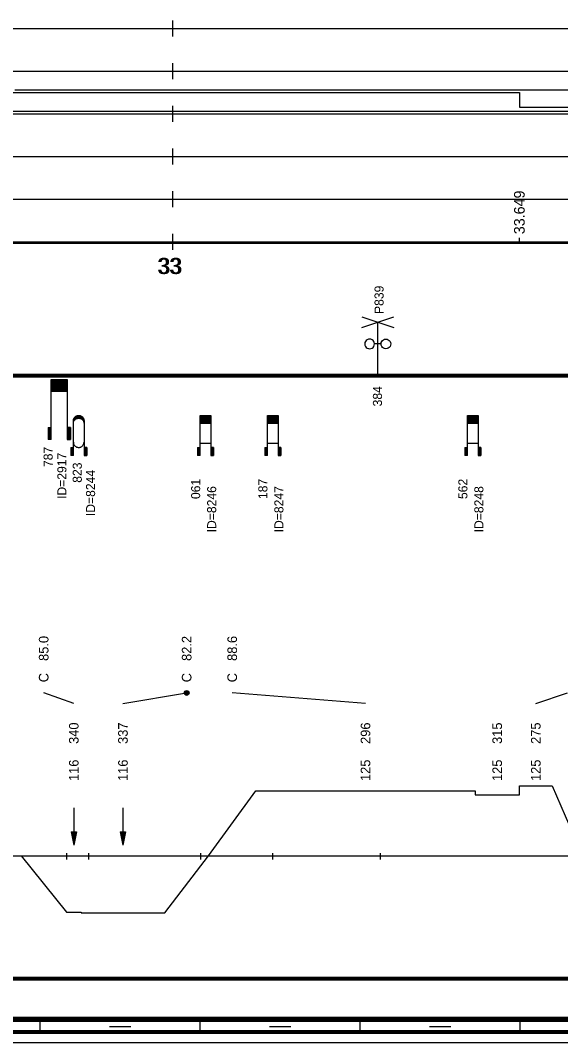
# Model space of a CAD drawing. Extents: x 2 to 10148, y 0 to 380.
# Drawn here: x 3571.3 to 3672.6, y 0 to 191.5 of the extents above; entities that cross this region are included whole.
import ezdxf

# ---------------------------------------------------------------- set-up
doc = ezdxf.new("R2010")
doc.units = 0
for name, color, linetype in [('CARA_S_OBJEKTY', 7, 'Continuous'), ('KRIV1_CARA', 7, 'Continuous'), ('KRIV1_TEXT', 7, 'Continuous'), ('OBJEKTY_TEXT', 7, 'Continuous'), ('OBJEKTY_TVAR', 7, 'Continuous'), ('RAM', 7, 'Continuous'), ('RYCHL_A', 7, 'Continuous'), ('RYCHL_B', 7, 'Continuous'), ('RYCHL_C', 7, 'Continuous'), ('RYCHL_RASTR', 7, 'Continuous'), ('RYCHL_STAN', 7, 'Continuous'), ('STAN_CARA', 7, 'Continuous'), ('STANIC_ZMEN_V', 7, 'Continuous')]:
    doc.layers.add(name, color=color, linetype=linetype)

msp = doc.modelspace()

# ---------------------------------------------------------------- linework, layer by layer
for p, q in [((3579.94, 35.51), (3579.94, 34.32)), ((3584.11, 35.51), (3584.11, 34.32)), ((3605.1, 35.51), (3605.1, 34.32)), ((3618.6, 35.51), (3618.6, 34.32)), ((3638.77, 35.51), (3638.77, 34.32))]:
    msp.add_line(p, q)
at = {"layer": 'CARA_S_OBJEKTY'}
for p, q in [((3155.54, 125.25), (4045.76, 125.25)), ((3155.54, 125), (4045.76, 125)), ((3155.54, 124.75), (4045.76, 124.75))]:
    msp.add_line(p, q, dxfattribs=at)
at = {"layer": 'KRIV1_CARA'}
for p, q in [((3664.85, 46.43), (3664.85, 48.09)), ((3664.85, 48.09), (3671, 48.09)), ((3671, 48.09), (3676.7, 35)), ((3606.59, 35), (3615.45, 47.16)), ((3615.45, 47.16), (3656.54, 47.16)), ((3656.54, 47.16), (3656.54, 46.43)), ((3656.54, 46.43), (3664.85, 46.43)), ((3155.54, 35), (4045.76, 35)), ((3571.43, 35), (3579.93, 24.41)), ((3598.37, 24.32), (3606.59, 35)), ((3579.93, 24.41), (3582.72, 24.41)), ((3582.72, 24.41), (3582.72, 24.32)), ((3582.72, 24.32), (3598.37, 24.32))]:
    msp.add_line(p, q, dxfattribs=at)
at = {"layer": 'KRIV1_TEXT'}
for p, q in [((3581.32, 63.5), (3575.68, 65.5)), ((3590.54, 63.5), (3602.48, 65.5)), ((3636, 63.5), (3611.02, 65.5)), ((3667.93, 63.5), (3673.85, 65.5)), ((3581.32, 44), (3581.32, 42.2)), ((3581.32, 42.2), (3581.32, 40)), ((3590.54, 44), (3590.54, 42.2)), ((3590.54, 42.2), (3590.54, 40)), ((3580.82, 39.5), (3581.32, 37)), ((3580.82, 39.5), (3581.82, 39.5)), ((3580.92, 39.5), (3581.32, 37.5)), ((3581.02, 39.5), (3581.32, 38)), ((3581.12, 39.5), (3581.32, 38.5)), ((3581.22, 39.5), (3581.32, 39)), ((3581.32, 40), (3581.32, 37)), ((3581.82, 39.5), (3581.32, 37)), ((3581.72, 39.5), (3581.32, 37.5)), ((3581.62, 39.5), (3581.32, 38)), ((3581.52, 39.5), (3581.32, 38.5)), ((3581.42, 39.5), (3581.32, 39)), ((3581.32, 39.5), (3581.32, 39.5)), ((3581.32, 39.5), (3581.32, 39.5)), ((3590.04, 39.5), (3590.54, 37)), ((3590.04, 39.5), (3591.04, 39.5)), ((3590.14, 39.5), (3590.54, 37.5)), ((3590.24, 39.5), (3590.54, 38)), ((3590.34, 39.5), (3590.54, 38.5)), ((3590.44, 39.5), (3590.54, 39)), ((3590.54, 40), (3590.54, 37)), ((3591.04, 39.5), (3590.54, 37)), ((3590.94, 39.5), (3590.54, 37.5)), ((3590.84, 39.5), (3590.54, 38)), ((3590.74, 39.5), (3590.54, 38.5)), ((3590.64, 39.5), (3590.54, 39)), ((3590.54, 39.5), (3590.54, 39.5)), ((3590.54, 39.5), (3590.54, 39.5))]:
    msp.add_line(p, q, dxfattribs=at)
for radius in [0.45, 0.3, 0.15]:
    msp.add_circle((3602.48, 65.5), radius, dxfattribs=at)
at = {"layer": 'OBJEKTY_TVAR'}
for p, q in [((3635.29, 134), (3641.29, 136)), ((3635.29, 136), (3641.29, 134)), ((3638.29, 125), (3638.29, 135)), ((3635.89, 131.13), (3635.86, 130.89)), ((3635.86, 130.89), (3635.89, 130.66)), ((3635.98, 131.35), (3635.89, 131.13)), ((3635.89, 130.66), (3635.98, 130.44)), ((3636.13, 131.54), (3635.98, 131.35)), ((3635.98, 130.44), (3636.13, 130.25)), ((3636.32, 131.68), (3636.13, 131.54)), ((3636.13, 130.25), (3636.32, 130.1)), ((3636.54, 131.77), (3636.32, 131.68)), ((3636.77, 131.81), (3636.54, 131.77)), ((3637.01, 131.77), (3636.77, 131.81)), ((3637.23, 131.68), (3637.01, 131.77)), ((3637.42, 131.54), (3637.23, 131.68)), ((3637.23, 130.1), (3637.42, 130.25)), ((3637.56, 131.35), (3637.42, 131.54)), ((3637.42, 130.25), (3637.56, 130.44)), ((3637.65, 131.13), (3637.56, 131.35)), ((3637.56, 130.44), (3637.65, 130.66)), ((3637.68, 130.89), (3637.65, 131.13)), ((3637.65, 130.66), (3637.68, 130.89)), ((3638.92, 130.89), (3637.68, 130.89)), ((3638.92, 130.89), (3638.95, 131.13)), ((3638.95, 130.66), (3638.92, 130.89)), ((3638.95, 131.13), (3639.04, 131.35)), ((3639.04, 130.44), (3638.95, 130.66)), ((3639.04, 131.35), (3639.18, 131.54)), ((3639.18, 130.25), (3639.04, 130.44)), ((3639.18, 131.54), (3639.37, 131.68)), ((3639.37, 130.1), (3639.18, 130.25)), ((3639.37, 131.68), (3639.59, 131.77)), ((3639.59, 131.77), (3639.83, 131.81)), ((3639.83, 131.81), (3640.06, 131.77)), ((3640.06, 131.77), (3640.28, 131.68)), ((3640.28, 131.68), (3640.47, 131.54)), ((3640.47, 130.25), (3640.28, 130.1)), ((3640.47, 131.54), (3640.62, 131.35)), ((3640.62, 130.44), (3640.47, 130.25)), ((3640.62, 131.35), (3640.71, 131.13)), ((3640.71, 130.66), (3640.62, 130.44)), ((3640.71, 131.13), (3640.74, 130.89)), ((3640.74, 130.89), (3640.71, 130.66)), ((3636.32, 130.1), (3636.54, 130.01)), ((3636.54, 130.01), (3636.77, 129.98)), ((3636.77, 129.98), (3637.01, 130.01)), ((3637.01, 130.01), (3637.23, 130.1)), ((3639.59, 130.01), (3639.37, 130.1)), ((3639.83, 129.98), (3639.59, 130.01)), ((3640.06, 130.01), (3639.83, 129.98)), ((3640.28, 130.1), (3640.06, 130.01)), ((3577.09, 124.25), (3580.09, 124.25)), ((3577.09, 113), (3577.09, 124.25)), ((3577.09, 124.17), (3580.09, 124.17)), ((3577.09, 124.1), (3580.09, 124.1)), ((3577.09, 124.02), (3580.09, 124.02)), ((3577.09, 123.95), (3580.09, 123.95)), ((3577.09, 123.87), (3580.09, 123.87)), ((3577.09, 123.8), (3580.09, 123.8)), ((3577.09, 123.72), (3580.09, 123.72)), ((3577.09, 123.65), (3580.09, 123.65)), ((3577.09, 123.57), (3580.09, 123.57)), ((3577.09, 123.5), (3580.09, 123.5)), ((3577.09, 123.42), (3580.09, 123.42)), ((3577.09, 123.35), (3580.09, 123.35)), ((3577.09, 123.27), (3580.09, 123.27)), ((3577.09, 123.2), (3580.09, 123.2)), ((3577.09, 123.12), (3580.09, 123.12)), ((3577.09, 123.05), (3580.09, 123.05)), ((3577.09, 122.97), (3580.09, 122.97)), ((3577.09, 122.9), (3580.09, 122.9)), ((3577.09, 122.82), (3580.09, 122.82)), ((3577.09, 122.75), (3580.09, 122.75)), ((3577.09, 122.67), (3580.09, 122.67)), ((3577.09, 122.6), (3580.09, 122.6)), ((3580.09, 124.25), (3580.09, 113)), ((3577.09, 122.52), (3580.09, 122.52)), ((3577.09, 122.45), (3580.09, 122.45)), ((3577.09, 122.37), (3580.09, 122.37)), ((3577.09, 122.3), (3580.09, 122.3)), ((3577.09, 122.22), (3580.09, 122.22)), ((3577.09, 122.15), (3580.09, 122.15)), ((3577.09, 122.07), (3580.09, 122.07)), ((3581.29, 116.81), (3581.35, 116.95)), ((3581.3, 116.85), (3581.75, 116.85)), ((3581.32, 116.9), (3581.86, 116.9)), ((3581.35, 116.95), (3581.41, 117.06)), ((3581.35, 116.95), (3582.01, 116.95)), ((3581.37, 117), (3583.11, 117)), ((3581.4, 117.05), (3583.08, 117.05)), ((3581.41, 117.06), (3581.5, 117.18)), ((3581.44, 117.1), (3583.04, 117.1)), ((3581.48, 117.15), (3583, 117.15)), ((3581.5, 117.18), (3581.59, 117.26)), ((3581.53, 117.2), (3582.95, 117.2)), ((3581.58, 117.25), (3582.9, 117.25)), ((3581.59, 117.26), (3581.72, 117.35)), ((3581.59, 116.74), (3581.72, 116.83)), ((3581.64, 117.3), (3582.84, 117.3)), ((3581.71, 117.35), (3582.77, 117.35)), ((3581.72, 117.35), (3581.85, 117.42)), ((3581.72, 116.83), (3581.85, 116.9)), ((3581.8, 117.4), (3582.68, 117.4)), ((3581.85, 117.42), (3581.88, 117.43)), ((3581.85, 116.9), (3581.88, 116.91)), ((3581.88, 117.43), (3582, 117.47)), ((3581.88, 116.91), (3582, 116.95)), ((3581.93, 117.45), (3582.55, 117.45)), ((3582, 117.47), (3582.14, 117.49)), ((3582, 116.95), (3582.14, 116.97)), ((3582.14, 117.49), (3582.25, 117.5)), ((3582.14, 116.97), (3582.25, 116.98)), ((3582.25, 117.5), (3582.38, 117.49)), ((3582.25, 116.98), (3582.38, 116.97)), ((3582.38, 117.49), (3582.51, 117.46)), ((3582.38, 116.97), (3582.51, 116.94)), ((3582.47, 116.95), (3583.13, 116.95)), ((3582.51, 117.46), (3582.62, 117.43)), ((3582.51, 116.94), (3582.62, 116.9)), ((3582.62, 117.43), (3582.73, 117.37)), ((3582.62, 116.9), (3582.73, 116.85)), ((3582.62, 116.9), (3583.16, 116.9)), ((3582.73, 117.37), (3582.8, 117.32)), ((3582.73, 116.85), (3583.18, 116.85)), ((3582.73, 116.85), (3582.8, 116.8)), ((3582.8, 117.32), (3582.95, 117.21)), ((3582.95, 117.21), (3583.03, 117.11)), ((3583.03, 117.11), (3583.12, 116.98)), ((3583.12, 116.98), (3583.16, 116.89)), ((3583.16, 116.89), (3583.2, 116.77)), ((3605.02, 110), (3605.02, 117.5)), ((3605.02, 117.5), (3607.02, 117.5)), ((3605.02, 117.45), (3607.02, 117.45)), ((3605.02, 117.4), (3607.02, 117.4)), ((3605.02, 117.35), (3607.02, 117.35)), ((3605.02, 117.3), (3607.02, 117.3)), ((3605.02, 117.25), (3607.02, 117.25)), ((3605.02, 117.2), (3607.02, 117.2)), ((3605.02, 117.15), (3607.02, 117.15)), ((3605.02, 117.1), (3607.02, 117.1)), ((3605.02, 117.05), (3607.02, 117.05)), ((3605.02, 117), (3607.02, 117)), ((3605.02, 116.95), (3607.02, 116.95)), ((3605.02, 116.9), (3607.02, 116.9)), ((3605.02, 116.85), (3607.02, 116.85)), ((3607.02, 117.5), (3607.02, 110)), ((3617.62, 110), (3617.62, 117.5)), ((3617.62, 117.5), (3619.62, 117.5)), ((3617.62, 117.45), (3619.62, 117.45)), ((3617.62, 117.4), (3619.62, 117.4)), ((3617.62, 117.35), (3619.62, 117.35)), ((3617.62, 117.3), (3619.62, 117.3)), ((3617.62, 117.25), (3619.62, 117.25)), ((3617.62, 117.2), (3619.62, 117.2)), ((3617.62, 117.15), (3619.62, 117.15)), ((3617.62, 117.1), (3619.62, 117.1)), ((3617.62, 117.05), (3619.62, 117.05)), ((3617.62, 117), (3619.62, 117)), ((3617.62, 116.95), (3619.62, 116.95)), ((3617.62, 116.9), (3619.62, 116.9)), ((3617.62, 116.85), (3619.62, 116.85)), ((3619.62, 117.5), (3619.62, 110)), ((3655.11, 110), (3655.11, 117.5)), ((3655.11, 117.5), (3657.11, 117.5)), ((3655.11, 117.45), (3657.11, 117.45)), ((3655.11, 117.4), (3657.11, 117.4)), ((3655.11, 117.35), (3657.11, 117.35)), ((3655.11, 117.3), (3657.11, 117.3)), ((3655.11, 117.25), (3657.11, 117.25)), ((3655.11, 117.2), (3657.11, 117.2)), ((3655.11, 117.15), (3657.11, 117.15)), ((3655.11, 117.1), (3657.11, 117.1)), ((3655.11, 117.05), (3657.11, 117.05)), ((3655.11, 117), (3657.11, 117)), ((3655.11, 116.95), (3657.11, 116.95)), ((3655.11, 116.9), (3657.11, 116.9)), ((3655.11, 116.85), (3657.11, 116.85)), ((3657.11, 117.5), (3657.11, 110)), ((3576.49, 115.25), (3576.49, 113)), ((3576.49, 115.25), (3577.09, 115.25)), ((3576.56, 115.25), (3576.56, 113)), ((3576.64, 115.25), (3576.64, 113)), ((3576.71, 115.25), (3576.71, 113)), ((3576.79, 115.25), (3576.79, 113)), ((3576.86, 115.25), (3576.86, 113)), ((3576.94, 115.25), (3576.94, 113)), ((3577.01, 115.25), (3577.01, 113)), ((3580.69, 115.25), (3580.09, 115.25)), ((3580.17, 115.25), (3580.17, 113)), ((3580.24, 115.25), (3580.24, 113)), ((3580.32, 115.25), (3580.32, 113)), ((3580.39, 115.25), (3580.39, 113)), ((3580.47, 115.25), (3580.47, 113)), ((3580.54, 115.25), (3580.54, 113)), ((3580.62, 115.25), (3580.62, 113)), ((3580.69, 115.25), (3580.69, 113)), ((3581.24, 116.5), (3581.25, 116.65)), ((3581.24, 116.55), (3581.42, 116.55)), ((3581.24, 110), (3581.24, 116.5)), ((3581.24, 116.5), (3581.39, 116.5)), ((3581.24, 116.45), (3581.36, 116.45)), ((3581.24, 116.4), (3581.33, 116.4)), ((3581.24, 116.35), (3581.31, 116.35)), ((3581.24, 116.3), (3581.29, 116.3)), ((3581.24, 116.25), (3581.28, 116.25)), ((3581.24, 116.2), (3581.27, 116.2)), ((3581.24, 116.15), (3581.26, 116.15)), ((3581.24, 115.98), (3581.25, 116.13)), ((3581.24, 116.1), (3581.25, 116.1)), ((3581.25, 116.65), (3581.29, 116.81)), ((3581.25, 116.65), (3581.5, 116.65)), ((3581.25, 116.6), (3581.46, 116.6)), ((3581.25, 116.13), (3581.29, 116.28)), ((3581.26, 116.7), (3581.55, 116.7)), ((3581.27, 116.75), (3581.61, 116.75)), ((3581.29, 116.8), (3581.67, 116.8)), ((3581.29, 116.28), (3581.35, 116.43)), ((3581.35, 116.43), (3581.41, 116.53)), ((3581.41, 116.53), (3581.5, 116.65)), ((3581.5, 116.65), (3581.59, 116.74)), ((3582.8, 116.8), (3582.95, 116.68)), ((3582.81, 116.8), (3583.19, 116.8)), ((3582.87, 116.75), (3583.21, 116.75)), ((3582.93, 116.7), (3583.22, 116.7)), ((3582.95, 116.68), (3583.03, 116.59)), ((3582.98, 116.65), (3583.23, 116.65)), ((3583.02, 116.6), (3583.23, 116.6)), ((3583.03, 116.59), (3583.12, 116.46)), ((3583.06, 116.55), (3583.24, 116.55)), ((3583.09, 116.5), (3583.24, 116.5)), ((3583.12, 116.46), (3583.16, 116.37)), ((3583.12, 116.45), (3583.24, 116.45)), ((3583.15, 116.4), (3583.24, 116.4)), ((3583.16, 116.37), (3583.2, 116.24)), ((3583.17, 116.35), (3583.24, 116.35)), ((3583.19, 116.3), (3583.24, 116.3)), ((3583.2, 116.77), (3583.23, 116.65)), ((3583.2, 116.25), (3583.24, 116.25)), ((3583.2, 116.24), (3583.23, 116.13)), ((3583.21, 116.2), (3583.24, 116.2)), ((3583.22, 116.15), (3583.24, 116.15)), ((3583.23, 116.65), (3583.24, 116.56)), ((3583.23, 116.13), (3583.24, 116.03)), ((3583.23, 116.1), (3583.24, 116.1)), ((3583.24, 116.56), (3583.24, 116.5)), ((3583.24, 116.5), (3583.24, 110)), ((3583.24, 116.03), (3583.24, 115.98)), ((3605.02, 116.8), (3607.02, 116.8)), ((3605.02, 116.75), (3607.02, 116.75)), ((3605.02, 116.7), (3607.02, 116.7)), ((3605.02, 116.65), (3607.02, 116.65)), ((3605.02, 116.6), (3607.02, 116.6)), ((3605.02, 116.55), (3607.02, 116.55)), ((3605.02, 116.5), (3607.02, 116.5)), ((3605.02, 116.45), (3607.02, 116.45)), ((3605.02, 116.4), (3607.02, 116.4)), ((3605.02, 116.35), (3607.02, 116.35)), ((3605.02, 116.3), (3607.02, 116.3)), ((3605.02, 116.25), (3607.02, 116.25)), ((3605.02, 116.2), (3607.02, 116.2)), ((3605.02, 116.15), (3607.02, 116.15)), ((3605.02, 116.1), (3607.02, 116.1)), ((3605.02, 116.05), (3607.02, 116.05)), ((3617.62, 116.8), (3619.62, 116.8)), ((3617.62, 116.75), (3619.62, 116.75)), ((3617.62, 116.7), (3619.62, 116.7)), ((3617.62, 116.65), (3619.62, 116.65)), ((3617.62, 116.6), (3619.62, 116.6)), ((3617.62, 116.55), (3619.62, 116.55)), ((3617.62, 116.5), (3619.62, 116.5)), ((3617.62, 116.45), (3619.62, 116.45)), ((3617.62, 116.4), (3619.62, 116.4)), ((3617.62, 116.35), (3619.62, 116.35)), ((3617.62, 116.3), (3619.62, 116.3)), ((3617.62, 116.25), (3619.62, 116.25)), ((3617.62, 116.2), (3619.62, 116.2)), ((3617.62, 116.15), (3619.62, 116.15)), ((3617.62, 116.1), (3619.62, 116.1)), ((3617.62, 116.05), (3619.62, 116.05)), ((3655.11, 116.8), (3657.11, 116.8)), ((3655.11, 116.75), (3657.11, 116.75)), ((3655.11, 116.7), (3657.11, 116.7)), ((3655.11, 116.65), (3657.11, 116.65)), ((3655.11, 116.6), (3657.11, 116.6)), ((3655.11, 116.55), (3657.11, 116.55)), ((3655.11, 116.5), (3657.11, 116.5)), ((3655.11, 116.45), (3657.11, 116.45)), ((3655.11, 116.4), (3657.11, 116.4)), ((3655.11, 116.35), (3657.11, 116.35)), ((3655.11, 116.3), (3657.11, 116.3)), ((3655.11, 116.25), (3657.11, 116.25)), ((3655.11, 116.2), (3657.11, 116.2)), ((3655.11, 116.15), (3657.11, 116.15)), ((3655.11, 116.1), (3657.11, 116.1)), ((3655.11, 116.05), (3657.11, 116.05)), ((3577.09, 113), (3576.49, 113)), ((3580.09, 113), (3580.69, 113)), ((3580.74, 111.5), (3581.24, 111.5)), ((3580.74, 111.5), (3580.74, 110)), ((3580.79, 111.5), (3580.79, 110)), ((3580.84, 111.5), (3580.84, 110)), ((3580.89, 111.5), (3580.89, 110)), ((3580.94, 111.5), (3580.94, 110)), ((3580.99, 111.5), (3580.99, 110)), ((3581.04, 111.5), (3581.04, 110)), ((3581.09, 111.5), (3581.09, 110)), ((3581.14, 111.5), (3581.14, 110)), ((3581.19, 111.5), (3581.19, 110)), ((3581.24, 112.5), (3581.25, 112.35)), ((3581.25, 112.35), (3581.29, 112.2)), ((3581.29, 112.2), (3581.35, 112.05)), ((3581.35, 112.05), (3581.41, 111.95)), ((3581.41, 111.95), (3581.5, 111.83)), ((3581.5, 111.83), (3581.59, 111.74)), ((3581.59, 111.74), (3581.72, 111.65)), ((3581.72, 111.65), (3581.85, 111.58)), ((3581.85, 111.58), (3581.88, 111.57)), ((3581.88, 111.57), (3582, 111.53)), ((3582, 111.53), (3582.14, 111.51)), ((3582.14, 111.51), (3582.25, 111.5)), ((3582.25, 111.5), (3582.38, 111.51)), ((3582.38, 111.51), (3582.51, 111.54)), ((3582.51, 111.54), (3582.62, 111.58)), ((3582.62, 111.58), (3582.73, 111.63)), ((3582.73, 111.63), (3582.8, 111.68)), ((3582.8, 111.68), (3582.95, 111.8)), ((3582.95, 111.8), (3583.03, 111.9)), ((3583.03, 111.9), (3583.12, 112.02)), ((3583.12, 112.02), (3583.16, 112.11)), ((3583.16, 112.11), (3583.2, 112.24)), ((3583.2, 112.24), (3583.23, 112.35)), ((3583.23, 112.35), (3583.24, 112.45)), ((3583.24, 112.45), (3583.24, 112.5)), ((3583.74, 111.5), (3583.24, 111.5)), ((3583.29, 111.5), (3583.29, 110)), ((3583.34, 111.5), (3583.34, 110)), ((3583.39, 111.5), (3583.39, 110)), ((3583.44, 111.5), (3583.44, 110)), ((3583.49, 111.5), (3583.49, 110)), ((3583.54, 111.5), (3583.54, 110)), ((3583.59, 111.5), (3583.59, 110)), ((3583.64, 111.5), (3583.64, 110)), ((3583.69, 111.5), (3583.69, 110)), ((3583.74, 111.5), (3583.74, 110)), ((3604.52, 111.5), (3605.02, 111.5)), ((3604.52, 111.5), (3604.52, 110)), ((3604.57, 111.5), (3604.57, 110)), ((3604.62, 111.5), (3604.62, 110)), ((3604.67, 111.5), (3604.67, 110)), ((3604.72, 111.5), (3604.72, 110)), ((3604.77, 111.5), (3604.77, 110)), ((3604.82, 111.5), (3604.82, 110)), ((3604.87, 111.5), (3604.87, 110)), ((3604.92, 111.5), (3604.92, 110)), ((3604.97, 111.5), (3604.97, 110)), ((3605.02, 112.31), (3607.02, 112.31)), ((3607.52, 111.5), (3607.02, 111.5)), ((3607.07, 111.5), (3607.07, 110)), ((3607.12, 111.5), (3607.12, 110)), ((3607.17, 111.5), (3607.17, 110)), ((3607.22, 111.5), (3607.22, 110)), ((3607.27, 111.5), (3607.27, 110)), ((3607.32, 111.5), (3607.32, 110)), ((3607.37, 111.5), (3607.37, 110)), ((3607.42, 111.5), (3607.42, 110)), ((3607.47, 111.5), (3607.47, 110)), ((3607.52, 111.5), (3607.52, 110)), ((3617.12, 111.5), (3617.62, 111.5)), ((3617.12, 111.5), (3617.12, 110)), ((3617.17, 111.5), (3617.17, 110)), ((3617.22, 111.5), (3617.22, 110)), ((3617.27, 111.5), (3617.27, 110)), ((3617.32, 111.5), (3617.32, 110)), ((3617.37, 111.5), (3617.37, 110)), ((3617.42, 111.5), (3617.42, 110)), ((3617.47, 111.5), (3617.47, 110)), ((3617.52, 111.5), (3617.52, 110)), ((3617.57, 111.5), (3617.57, 110)), ((3617.62, 112.31), (3619.62, 112.31)), ((3620.12, 111.5), (3619.62, 111.5)), ((3619.67, 111.5), (3619.67, 110)), ((3619.72, 111.5), (3619.72, 110)), ((3619.77, 111.5), (3619.77, 110)), ((3619.82, 111.5), (3619.82, 110)), ((3619.87, 111.5), (3619.87, 110)), ((3619.92, 111.5), (3619.92, 110)), ((3619.97, 111.5), (3619.97, 110)), ((3620.02, 111.5), (3620.02, 110)), ((3620.07, 111.5), (3620.07, 110)), ((3620.12, 111.5), (3620.12, 110)), ((3654.61, 111.5), (3655.11, 111.5)), ((3654.61, 111.5), (3654.61, 110)), ((3654.66, 111.5), (3654.66, 110)), ((3654.71, 111.5), (3654.71, 110)), ((3654.76, 111.5), (3654.76, 110)), ((3654.81, 111.5), (3654.81, 110)), ((3654.86, 111.5), (3654.86, 110)), ((3654.91, 111.5), (3654.91, 110)), ((3654.96, 111.5), (3654.96, 110)), ((3655.01, 111.5), (3655.01, 110)), ((3655.06, 111.5), (3655.06, 110)), ((3655.11, 112.31), (3657.11, 112.31)), ((3657.61, 111.5), (3657.11, 111.5)), ((3657.16, 111.5), (3657.16, 110)), ((3657.21, 111.5), (3657.21, 110)), ((3657.26, 111.5), (3657.26, 110)), ((3657.31, 111.5), (3657.31, 110)), ((3657.36, 111.5), (3657.36, 110)), ((3657.41, 111.5), (3657.41, 110)), ((3657.46, 111.5), (3657.46, 110)), ((3657.51, 111.5), (3657.51, 110)), ((3657.56, 111.5), (3657.56, 110)), ((3657.61, 111.5), (3657.61, 110)), ((3581.24, 110), (3580.74, 110)), ((3583.24, 110), (3583.74, 110)), ((3605.02, 110), (3604.52, 110)), ((3607.02, 110), (3607.52, 110)), ((3617.62, 110), (3617.12, 110)), ((3619.62, 110), (3620.12, 110)), ((3655.11, 110), (3654.61, 110)), ((3657.11, 110), (3657.61, 110))]:
    msp.add_line(p, q, dxfattribs=at)
at = {"layer": 'RAM'}
for p, q in [((3155.54, 4.75), (4045.76, 4.75)), ((3155.54, 4.5), (4045.76, 4.5)), ((3155.54, 4.25), (4045.76, 4.25)), ((3155.54, 4), (4045.76, 4)), ((3575, 2), (3575, 4)), ((3605, 2), (3605, 4)), ((3635, 2), (3635, 4)), ((3665, 2), (3665, 4)), ((3155.54, 2.25), (4045.76, 2.25)), ((3155.54, 2), (4045.76, 2)), ((3588, 3), (3592, 3)), ((3618, 3), (3622, 3)), ((3648, 3), (3652, 3)), ((3155.54, 1.75), (4045.76, 1.75)), ((3155.54, 0), (4045.76, 0))]:
    msp.add_line(p, q, dxfattribs=at)
at = {"layer": 'RYCHL_A'}
msp.add_line((3156.9, 174.5), (3782.41, 174.5), dxfattribs=at)
at = {"layer": 'RYCHL_B'}
for p, q in [((3155.54, 178), (3664.85, 178)), ((3664.85, 178), (3664.85, 175.25)), ((3664.85, 175.25), (3676.7, 175.25))]:
    msp.add_line(p, q, dxfattribs=at)
at = {"layer": 'RYCHL_C'}
msp.add_line((3570.27, 178.53), (3675.95, 178.53), dxfattribs=at)
at = {"layer": 'RYCHL_RASTR'}
for p, q in [((3599.91, 188.5), (3599.91, 191.5)), ((3155.54, 190), (4046.94, 190)), ((3155.54, 182), (4047.3, 182)), ((3599.91, 180.5), (3599.91, 183.5)), ((3599.91, 172.5), (3599.91, 175.5)), ((3155.54, 174), (4047.27, 174)), ((3599.91, 164.5), (3599.91, 167.5)), ((3155.54, 166), (4047.1, 166)), ((3599.91, 156.5), (3599.91, 159.5)), ((3155.54, 158), (4047.25, 158)), ((3599.91, 148.5), (3599.91, 151.5)), ((3155.54, 150), (4045.76, 150)), ((3155.54, 149.75), (4045.76, 149.75))]:
    msp.add_line(p, q, dxfattribs=at)
at = {"layer": 'STAN_CARA'}
for p, q in [((3301.41, 12.25), (3798.41, 12.25)), ((3301.41, 12), (3798.41, 12)), ((3301.41, 12), (3798.41, 12)), ((3301.41, 11.75), (3798.41, 11.75))]:
    msp.add_line(p, q, dxfattribs=at)
at = {"layer": 'STANIC_ZMEN_V'}
msp.add_line((3664.85, 150), (3664.85, 150.75), dxfattribs=at)

# ---------------------------------------------------------------- texts
at = {"layer": 'KRIV1_TEXT'}
for s, p in [('85.0', (3576.58, 71.5)), ('82.2', (3603.38, 71.5)), ('88.6', (3611.92, 71.5)), ('C', (3576.58, 67.5)), ('C', (3603.38, 67.5)), ('C', (3611.92, 67.5)), ('340', (3582.22, 55.95)), ('337', (3591.44, 55.95)), ('296', (3636.9, 55.95)), ('315', (3661.6, 55.95)), ('275', (3668.83, 55.95)), ('116', (3582.22, 49)), ('116', (3591.44, 49)), ('125', (3636.9, 49)), ('125', (3661.6, 49)), ('125', (3668.83, 49))]:
    msp.add_text(s, height=1.8, rotation=90, dxfattribs=at).set_placement(p)
at = {"layer": 'OBJEKTY_TEXT'}
for s, p in [('P839', (3639.4, 136.5)), ('384', (3639.1, 119.19)), ('787', (3577.36, 107.83)), ('ID=2917', (3579.94, 101.85)), ('823', (3582.82, 104.88)), ('ID=8244', (3585.32, 98.63)), ('061', (3605.02, 101.83)), ('187', (3617.62, 101.83)), ('562', (3655.11, 101.83)), ('ID=8246', (3608.02, 95.59)), ('ID=8247', (3620.62, 95.59)), ('ID=8248', (3658.11, 95.59))]:
    msp.add_text(s, height=1.7, rotation=90, dxfattribs=at).set_placement(p)
at = {"layer": 'RYCHL_STAN'}
for p in [(3596.97, 144), (3597.22, 144)]:
    msp.add_text('33', height=3, dxfattribs=at).set_placement(p)
at = {"layer": 'STANIC_ZMEN_V'}
msp.add_text('33.649', height=2, rotation=90, dxfattribs=at).set_placement((3665.85, 151.45))

doc.saveas('drawing.dxf')
